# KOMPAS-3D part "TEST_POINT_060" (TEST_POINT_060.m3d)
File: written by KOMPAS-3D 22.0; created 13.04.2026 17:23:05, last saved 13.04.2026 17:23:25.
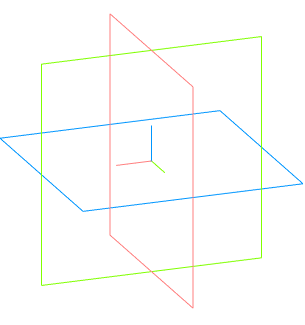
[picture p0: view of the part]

Document properties: Автор: Andrey; Полное имя файла: C:\Users\User1\Documents\Работа\Корпуса\Корпус Repka Pi 5\Конструкторская документация\3д модель\Repka_5_3D\TEST_POINT_060.m3d

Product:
- Part/product: TEST_POINT_060
    Комментарий: TEST_POINT_060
